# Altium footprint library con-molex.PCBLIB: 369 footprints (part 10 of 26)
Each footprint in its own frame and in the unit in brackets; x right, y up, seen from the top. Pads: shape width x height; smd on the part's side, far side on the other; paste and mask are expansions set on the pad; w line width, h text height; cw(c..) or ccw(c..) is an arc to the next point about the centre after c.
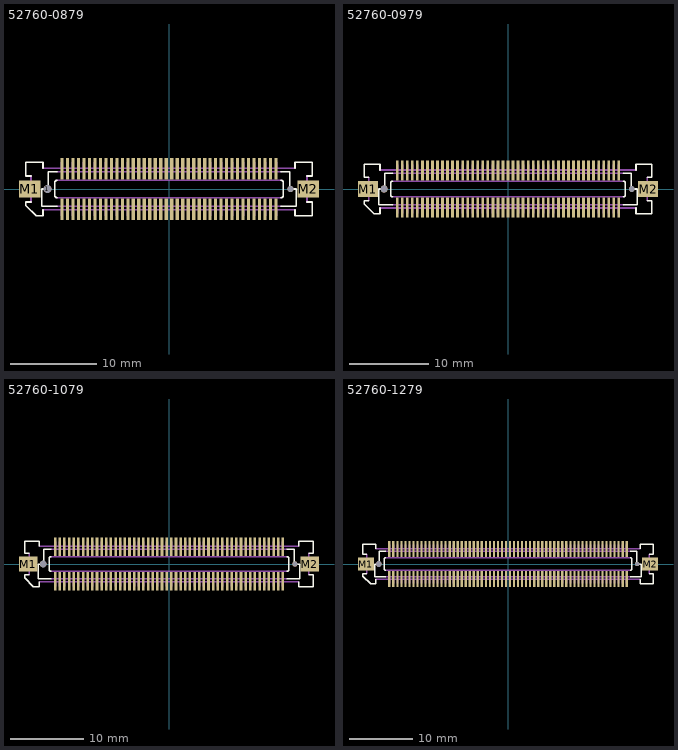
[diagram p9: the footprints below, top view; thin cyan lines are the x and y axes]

## 52760-0879 [mm]
pads (84):
  round 0.9 hole 0.9: 1(-14.035,0)
  rect 0.35x2.5 smd: 1(-12.383,-2.35) 2(-12.383,2.35) 3(-11.747,-2.35) 4(-11.747,2.35) 5(-11.112,-2.35) 6(-11.112,2.35) 7(-10.477,-2.35) 8(-10.477,2.35) 9(-9.842,-2.35) 10(-9.842,2.35) 11(-9.207,-2.35) 12(-9.207,2.35) 13(-8.572,-2.35) 14(-8.572,2.35) 15(-7.938,-2.35) 16(-7.938,2.35) 17(-7.302,-2.35) 18(-7.302,2.35) 19(-6.667,-2.35) 20(-6.667,2.35) 21(-6.032,-2.35) 22(-6.032,2.35) 23(-5.397,-2.35) 24(-5.397,2.35) 25(-4.763,-2.35) 26(-4.763,2.35) 27(-4.127,-2.35) 28(-4.127,2.35) 29(-3.492,-2.35) 30(-3.492,2.35) 31(-2.857,-2.35) 32(-2.857,2.35) 33(-2.222,-2.35) 34(-2.222,2.35) 35(-1.587,-2.35) 36(-1.587,2.35) 37(-0.953,-2.35) 38(-0.953,2.35) 39(-0.318,-2.35) 40(-0.318,2.35) 41(0.318,-2.35) 42(0.318,2.35) 43(0.953,-2.35) 44(0.953,2.35) 45(1.587,-2.35) 46(1.587,2.35) 47(2.222,-2.35) 48(2.222,2.35) 49(2.857,-2.35) 50(2.857,2.35) 51(3.492,-2.35) 52(3.492,2.35) 53(4.127,-2.35) 54(4.127,2.35) 55(4.763,-2.35) 56(4.763,2.35) 57(5.397,-2.35) 58(5.397,2.35) 59(6.032,-2.35) 60(6.032,2.35) 61(6.667,-2.35) 62(6.667,2.35) 63(7.302,-2.35) 64(7.302,2.35) 65(7.938,-2.35) 66(7.938,2.35) 67(8.572,-2.35) 68(8.572,2.35) 69(9.207,-2.35) 70(9.207,2.35) 71(9.842,-2.35) 72(9.842,2.35) 73(10.477,-2.35) 74(10.477,2.35) 75(11.112,-2.35) 76(11.112,2.35) 77(11.747,-2.35) 78(11.747,2.35) 79(12.383,-2.35) 80(12.383,2.35)
  round 0.7 hole 0.7: 1(14.035,0)
  rect 2.5x2 smd: M1(-16.075,0) M2(16.075,0)
Top Overlay:
  lines w0.203: -15.95,-1.5 -16.55,-1.5 -16.55,-1.9 -15.35,-3.1 -14.55,-3.1 -14.55,-2.4 ; -15.95,1.5 -16.55,1.5 -16.55,3.1 -14.55,3.1 -14.55,2.4 ; -12.95,-2 -14.7,-2 -14.7,0 -13.95,0 -13.95,2 -12.95,2 ; -12.95,-1 cw(c-12.95,-0.75) -13.2,-0.75 -13.2,0.75 cw(c-12.95,0.75) -12.95,1 ; 12.95,-2 14.7,-2 14.7,0 13.95,0 13.95,2 12.95,2 ; 12.95,-1 ccw(c12.95,-0.75) 13.2,-0.75 13.2,0.75 ccw(c12.95,0.75) 12.95,1 ; 14.55,-2.4 14.55,-3.1 16.55,-3.1 16.55,-1.5 15.95,-1.5 ; 14.55,2.4 14.55,3.1 16.55,3.1 16.55,1.5 15.95,1.5
Top Solder:
  rectangle: -12.582,-3.625 -12.183,-1.075
  region: -12.183,3.625 -12.582,3.625 -12.582,1.075 -12.183,1.075
  rectangle: -11.947,-3.625 -11.548,-1.075
  region: -11.548,3.625 -11.947,3.625 -11.947,1.075 -11.548,1.075
  rectangle: -11.312,-3.625 -10.913,-1.075
  region: -10.913,3.625 -11.312,3.625 -11.312,1.075 -10.913,1.075
  rectangle: -10.677,-3.625 -10.278,-1.075
  region: -10.278,3.625 -10.677,3.625 -10.677,1.075 -10.278,1.075
  rectangle: -10.042,-3.625 -9.643,-1.075
  region: -9.643,3.625 -10.042,3.625 -10.042,1.075 -9.643,1.075
  rectangle: -9.407,-3.625 -9.008,-1.075
  region: -9.008,3.625 -9.407,3.625 -9.407,1.075 -9.008,1.075
  rectangle: -8.772,-3.625 -8.373,-1.075
  region: -8.373,3.625 -8.772,3.625 -8.772,1.075 -8.373,1.075
  rectangle: -8.137,-3.625 -7.738,-1.075
  region: -7.738,3.625 -8.137,3.625 -8.137,1.075 -7.738,1.075
  rectangle: -7.502,-3.625 -7.103,-1.075
  region: -7.103,3.625 -7.502,3.625 -7.502,1.075 -7.103,1.075
  rectangle: -6.867,-3.625 -6.468,-1.075
  region: -6.468,3.625 -6.867,3.625 -6.867,1.075 -6.468,1.075
  rectangle: -6.232,-3.625 -5.833,-1.075
  region: -5.833,3.625 -6.232,3.625 -6.232,1.075 -5.833,1.075
  rectangle: -5.597,-3.625 -5.198,-1.075
  region: -5.198,3.625 -5.597,3.625 -5.597,1.075 -5.198,1.075
  rectangle: -4.962,-3.625 -4.563,-1.075
  region: -4.563,3.625 -4.962,3.625 -4.962,1.075 -4.563,1.075
  rectangle: -4.327,-3.625 -3.928,-1.075
  region: -3.928,3.625 -4.327,3.625 -4.327,1.075 -3.928,1.075
  rectangle: -3.692,-3.625 -3.293,-1.075
  region: -3.293,3.625 -3.692,3.625 -3.692,1.075 -3.293,1.075
  rectangle: -3.057,-3.625 -2.658,-1.075
  region: -2.658,3.625 -3.057,3.625 -3.057,1.075 -2.658,1.075
  rectangle: -2.422,-3.625 -2.023,-1.075
  region: -2.023,3.625 -2.422,3.625 -2.422,1.075 -2.023,1.075
  rectangle: -1.787,-3.625 -1.388,-1.075
  region: -1.388,3.625 -1.787,3.625 -1.787,1.075 -1.388,1.075
  rectangle: -1.152,-3.625 -0.753,-1.075
  region: -0.753,3.625 -1.152,3.625 -1.152,1.075 -0.753,1.075
  rectangle: -0.517,-3.625 -0.118,-1.075
  region: -0.118,3.625 -0.517,3.625 -0.517,1.075 -0.118,1.075
  rectangle: 0.118,-3.625 0.517,-1.075
  region: 0.517,3.625 0.118,3.625 0.118,1.075 0.517,1.075
  rectangle: 0.753,-3.625 1.152,-1.075
  region: 1.152,3.625 0.753,3.625 0.753,1.075 1.152,1.075
  rectangle: 1.388,-3.625 1.787,-1.075
  region: 1.787,3.625 1.388,3.625 1.388,1.075 1.787,1.075
  rectangle: 2.023,-3.625 2.422,-1.075
  region: 2.422,3.625 2.023,3.625 2.023,1.075 2.422,1.075
  rectangle: 2.658,-3.625 3.057,-1.075
  region: 3.057,3.625 2.658,3.625 2.658,1.075 3.057,1.075
  rectangle: 3.293,-3.625 3.692,-1.075
  region: 3.692,3.625 3.293,3.625 3.293,1.075 3.692,1.075
  rectangle: 3.928,-3.625 4.327,-1.075
  region: 4.327,3.625 3.928,3.625 3.928,1.075 4.327,1.075
  rectangle: 4.563,-3.625 4.962,-1.075
  region: 4.962,3.625 4.563,3.625 4.563,1.075 4.962,1.075
  rectangle: 5.198,-3.625 5.597,-1.075
  region: 5.597,3.625 5.198,3.625 5.198,1.075 5.597,1.075
  rectangle: 5.833,-3.625 6.232,-1.075
  region: 6.232,3.625 5.833,3.625 5.833,1.075 6.232,1.075
  rectangle: 6.468,-3.625 6.867,-1.075
  region: 6.867,3.625 6.468,3.625 6.468,1.075 6.867,1.075
  rectangle: 7.103,-3.625 7.502,-1.075
  region: 7.502,3.625 7.103,3.625 7.103,1.075 7.502,1.075
  rectangle: 7.738,-3.625 8.137,-1.075
  region: 8.137,3.625 7.738,3.625 7.738,1.075 8.137,1.075
  rectangle: 8.373,-3.625 8.772,-1.075
  region: 8.772,3.625 8.373,3.625 8.373,1.075 8.772,1.075
  rectangle: 9.008,-3.625 9.407,-1.075
  region: 9.407,3.625 9.008,3.625 9.008,1.075 9.407,1.075
  rectangle: 9.643,-3.625 10.042,-1.075
  region: 10.042,3.625 9.643,3.625 9.643,1.075 10.042,1.075
  rectangle: 10.278,-3.625 10.677,-1.075
  region: 10.677,3.625 10.278,3.625 10.278,1.075 10.677,1.075
  rectangle: 10.913,-3.625 11.312,-1.075
  region: 11.312,3.625 10.913,3.625 10.913,1.075 11.312,1.075
  rectangle: 11.548,-3.625 11.947,-1.075
  region: 11.947,3.625 11.548,3.625 11.548,1.075 11.947,1.075
  rectangle: 12.183,-3.625 12.582,-1.075
  region: 12.582,3.625 12.183,3.625 12.183,1.075 12.582,1.075
Mechanical 16:
  rectangle: -12.533,-3.1 -12.232,-2.375
  region: -12.232,3.1 -12.533,3.1 -12.533,2.375 -12.232,2.375
  rectangle: -11.898,-3.1 -11.597,-2.375
  region: -11.597,3.1 -11.898,3.1 -11.898,2.375 -11.597,2.375
  rectangle: -11.263,-3.1 -10.962,-2.375
  region: -10.962,3.1 -11.263,3.1 -11.263,2.375 -10.962,2.375
  rectangle: -10.628,-3.1 -10.327,-2.375
  region: -10.327,3.1 -10.628,3.1 -10.628,2.375 -10.327,2.375
  rectangle: -9.993,-3.1 -9.692,-2.375
  region: -9.692,3.1 -9.993,3.1 -9.993,2.375 -9.692,2.375
  rectangle: -9.358,-3.1 -9.057,-2.375
  region: -9.057,3.1 -9.358,3.1 -9.358,2.375 -9.057,2.375
  rectangle: -8.723,-3.1 -8.422,-2.375
  region: -8.422,3.1 -8.723,3.1 -8.723,2.375 -8.422,2.375
  rectangle: -8.088,-3.1 -7.787,-2.375
  region: -7.787,3.1 -8.088,3.1 -8.088,2.375 -7.787,2.375
  rectangle: -7.453,-3.1 -7.152,-2.375
  region: -7.152,3.1 -7.453,3.1 -7.453,2.375 -7.152,2.375
  rectangle: -6.818,-3.1 -6.517,-2.375
  region: -6.517,3.1 -6.818,3.1 -6.818,2.375 -6.517,2.375
  rectangle: -6.183,-3.1 -5.882,-2.375
  region: -5.882,3.1 -6.183,3.1 -6.183,2.375 -5.882,2.375
  rectangle: -5.548,-3.1 -5.247,-2.375
  region: -5.247,3.1 -5.548,3.1 -5.548,2.375 -5.247,2.375
  rectangle: -4.913,-3.1 -4.612,-2.375
  region: -4.612,3.1 -4.913,3.1 -4.913,2.375 -4.612,2.375
  rectangle: -4.278,-3.1 -3.977,-2.375
  region: -3.977,3.1 -4.278,3.1 -4.278,2.375 -3.977,2.375
  rectangle: -3.643,-3.1 -3.342,-2.375
  region: -3.342,3.1 -3.643,3.1 -3.643,2.375 -3.342,2.375
  rectangle: -3.008,-3.1 -2.707,-2.375
  region: -2.707,3.1 -3.008,3.1 -3.008,2.375 -2.707,2.375
  rectangle: -2.373,-3.1 -2.072,-2.375
  region: -2.072,3.1 -2.373,3.1 -2.373,2.375 -2.072,2.375
  rectangle: -1.738,-3.1 -1.437,-2.375
  region: -1.437,3.1 -1.738,3.1 -1.738,2.375 -1.437,2.375
  rectangle: -1.103,-3.1 -0.802,-2.375
  region: -0.802,3.1 -1.103,3.1 -1.103,2.375 -0.802,2.375
  rectangle: -0.468,-3.1 -0.167,-2.375
  region: -0.167,3.1 -0.468,3.1 -0.468,2.375 -0.167,2.375
  rectangle: 0.167,-3.1 0.468,-2.375
  region: 0.468,3.1 0.167,3.1 0.167,2.375 0.468,2.375
  rectangle: 0.802,-3.1 1.103,-2.375
  region: 1.103,3.1 0.802,3.1 0.802,2.375 1.103,2.375
  rectangle: 1.437,-3.1 1.738,-2.375
  region: 1.738,3.1 1.437,3.1 1.437,2.375 1.738,2.375
  rectangle: 2.072,-3.1 2.373,-2.375
  region: 2.373,3.1 2.072,3.1 2.072,2.375 2.373,2.375
  rectangle: 2.707,-3.1 3.008,-2.375
  region: 3.008,3.1 2.707,3.1 2.707,2.375 3.008,2.375
  rectangle: 3.342,-3.1 3.643,-2.375
  region: 3.643,3.1 3.342,3.1 3.342,2.375 3.643,2.375
  rectangle: 3.977,-3.1 4.278,-2.375
  region: 4.278,3.1 3.977,3.1 3.977,2.375 4.278,2.375
  rectangle: 4.612,-3.1 4.913,-2.375
  region: 4.913,3.1 4.612,3.1 4.612,2.375 4.913,2.375
  rectangle: 5.247,-3.1 5.548,-2.375
  region: 5.548,3.1 5.247,3.1 5.247,2.375 5.548,2.375
  rectangle: 5.882,-3.1 6.183,-2.375
  region: 6.183,3.1 5.882,3.1 5.882,2.375 6.183,2.375
  rectangle: 6.517,-3.1 6.818,-2.375
  region: 6.818,3.1 6.517,3.1 6.517,2.375 6.818,2.375
  rectangle: 7.152,-3.1 7.453,-2.375
  region: 7.453,3.1 7.152,3.1 7.152,2.375 7.453,2.375
  rectangle: 7.787,-3.1 8.088,-2.375
  region: 8.088,3.1 7.787,3.1 7.787,2.375 8.088,2.375
  rectangle: 8.422,-3.1 8.723,-2.375
  region: 8.723,3.1 8.422,3.1 8.422,2.375 8.723,2.375
  rectangle: 9.057,-3.1 9.358,-2.375
  region: 9.358,3.1 9.057,3.1 9.057,2.375 9.358,2.375
  rectangle: 9.692,-3.1 9.993,-2.375
  region: 9.993,3.1 9.692,3.1 9.692,2.375 9.993,2.375
  rectangle: 10.327,-3.1 10.628,-2.375
  region: 10.628,3.1 10.327,3.1 10.327,2.375 10.628,2.375
  rectangle: 10.962,-3.1 11.263,-2.375
  region: 11.263,3.1 10.962,3.1 10.962,2.375 11.263,2.375
  rectangle: 11.597,-3.1 11.898,-2.375
  region: 11.898,3.1 11.597,3.1 11.597,2.375 11.898,2.375
  rectangle: 12.232,-3.1 12.533,-2.375
  region: 12.533,3.1 12.232,3.1 12.232,2.375 12.533,2.375
  lines w0.203: -15.95,-1.5 -15.95,1.5 ; -14.55,-2.4 14.55,-2.4 ; -14.55,2.4 14.55,2.4 ; -12.95,-2 12.95,-2 ; -12.95,-1 12.95,-1 ; -12.95,1 12.95,1 ; -12.95,2 12.95,2 ; 15.95,-1.5 15.95,1.5

## 52760-0979 [mm]
pads (94):
  round 0.9 hole 0.9: 1(-15.623,0)
  rect 0.35x2.5 smd: 1(-13.97,-2.35) 2(-13.97,2.35) 3(-13.335,-2.35) 4(-13.335,2.35) 5(-12.7,-2.35) 6(-12.7,2.35) 7(-12.065,-2.35) 8(-12.065,2.35) 9(-11.43,-2.35) 10(-11.43,2.35) 11(-10.795,-2.35) 12(-10.795,2.35) 13(-10.16,-2.35) 14(-10.16,2.35) 15(-9.525,-2.35) 16(-9.525,2.35) 17(-8.89,-2.35) 18(-8.89,2.35) 19(-8.255,-2.35) 20(-8.255,2.35) 21(-7.62,-2.35) 22(-7.62,2.35) 23(-6.985,-2.35) 24(-6.985,2.35) 25(-6.35,-2.35) 26(-6.35,2.35) 27(-5.715,-2.35) 28(-5.715,2.35) 29(-5.08,-2.35) 30(-5.08,2.35) 31(-4.445,-2.35) 32(-4.445,2.35) 33(-3.81,-2.35) 34(-3.81,2.35) 35(-3.175,-2.35) 36(-3.175,2.35) 37(-2.54,-2.35) 38(-2.54,2.35) 39(-1.905,-2.35) 40(-1.905,2.35) 41(-1.27,-2.35) 42(-1.27,2.35) 43(-0.635,-2.35) 44(-0.635,2.35) 45(0,-2.35) 46(0,2.35) 47(0.635,-2.35) 48(0.635,2.35) 49(1.27,-2.35) 50(1.27,2.35) 51(1.905,-2.35) 52(1.905,2.35) 53(2.54,-2.35) 54(2.54,2.35) 55(3.175,-2.35) 56(3.175,2.35) 57(3.81,-2.35) 58(3.81,2.35) 59(4.445,-2.35) 60(4.445,2.35) 61(5.08,-2.35) 62(5.08,2.35) 63(5.715,-2.35) 64(5.715,2.35) 65(6.35,-2.35) 66(6.35,2.35) 67(6.985,-2.35) 68(6.985,2.35) 69(7.62,-2.35) 70(7.62,2.35) 71(8.255,-2.35) 72(8.255,2.35) 73(8.89,-2.35) 74(8.89,2.35) 75(9.525,-2.35) 76(9.525,2.35) 77(10.16,-2.35) 78(10.16,2.35) 79(10.795,-2.35) 80(10.795,2.35) 81(11.43,-2.35) 82(11.43,2.35) 83(12.065,-2.35) 84(12.065,2.35) 85(12.7,-2.35) 86(12.7,2.35) 87(13.335,-2.35) 88(13.335,2.35) 89(13.97,-2.35) 90(13.97,2.35)
  round 0.7 hole 0.7: 1(15.623,0)
  rect 2.5x2 smd: M1(-17.662,0) M2(17.662,0)
Top Overlay:
  lines w0.203: -17.537,-1.5 -18.137,-1.5 -18.137,-1.9 -16.937,-3.1 -16.137,-3.1 -16.137,-2.4 ; -17.537,1.5 -18.137,1.5 -18.137,3.1 -16.137,3.1 -16.137,2.4 ; -14.537,-2 -16.287,-2 -16.287,0 -15.537,0 -15.537,2 -14.537,2 ; -14.537,-1 cw(c-14.538,-0.75) -14.788,-0.75 -14.788,0.75 cw(c-14.538,0.75) -14.537,1 ; 14.537,-2 16.287,-2 16.287,0 15.537,0 15.537,2 14.537,2 ; 14.537,-1 ccw(c14.538,-0.75) 14.788,-0.75 14.788,0.75 ccw(c14.538,0.75) 14.537,1 ; 16.137,-2.4 16.137,-3.1 18.137,-3.1 18.137,-1.5 17.537,-1.5 ; 16.137,2.4 16.137,3.1 18.137,3.1 18.137,1.5 17.537,1.5
Top Solder:
  rectangle: -14.17,-3.625 -13.77,-1.075
  region: -13.77,3.625 -14.17,3.625 -14.17,1.075 -13.77,1.075
  rectangle: -13.535,-3.625 -13.135,-1.075
  region: -13.135,3.625 -13.535,3.625 -13.535,1.075 -13.135,1.075
  rectangle: -12.9,-3.625 -12.5,-1.075
  region: -12.5,3.625 -12.9,3.625 -12.9,1.075 -12.5,1.075
  rectangle: -12.265,-3.625 -11.865,-1.075
  region: -11.865,3.625 -12.265,3.625 -12.265,1.075 -11.865,1.075
  rectangle: -11.63,-3.625 -11.23,-1.075
  region: -11.23,3.625 -11.63,3.625 -11.63,1.075 -11.23,1.075
  rectangle: -10.995,-3.625 -10.595,-1.075
  region: -10.595,3.625 -10.995,3.625 -10.995,1.075 -10.595,1.075
  rectangle: -10.36,-3.625 -9.96,-1.075
  region: -9.96,3.625 -10.36,3.625 -10.36,1.075 -9.96,1.075
  rectangle: -9.725,-3.625 -9.325,-1.075
  region: -9.325,3.625 -9.725,3.625 -9.725,1.075 -9.325,1.075
  rectangle: -9.09,-3.625 -8.69,-1.075
  region: -8.69,3.625 -9.09,3.625 -9.09,1.075 -8.69,1.075
  rectangle: -8.455,-3.625 -8.055,-1.075
  region: -8.055,3.625 -8.455,3.625 -8.455,1.075 -8.055,1.075
  rectangle: -7.82,-3.625 -7.42,-1.075
  region: -7.42,3.625 -7.82,3.625 -7.82,1.075 -7.42,1.075
  rectangle: -7.185,-3.625 -6.785,-1.075
  region: -6.785,3.625 -7.185,3.625 -7.185,1.075 -6.785,1.075
  rectangle: -6.55,-3.625 -6.15,-1.075
  region: -6.15,3.625 -6.55,3.625 -6.55,1.075 -6.15,1.075
  rectangle: -5.915,-3.625 -5.515,-1.075
  region: -5.515,3.625 -5.915,3.625 -5.915,1.075 -5.515,1.075
  rectangle: -5.28,-3.625 -4.88,-1.075
  region: -4.88,3.625 -5.28,3.625 -5.28,1.075 -4.88,1.075
  rectangle: -4.645,-3.625 -4.245,-1.075
  region: -4.245,3.625 -4.645,3.625 -4.645,1.075 -4.245,1.075
  rectangle: -4.01,-3.625 -3.61,-1.075
  region: -3.61,3.625 -4.01,3.625 -4.01,1.075 -3.61,1.075
  rectangle: -3.375,-3.625 -2.975,-1.075
  region: -2.975,3.625 -3.375,3.625 -3.375,1.075 -2.975,1.075
  rectangle: -2.74,-3.625 -2.34,-1.075
  region: -2.34,3.625 -2.74,3.625 -2.74,1.075 -2.34,1.075
  rectangle: -2.105,-3.625 -1.705,-1.075
  region: -1.705,3.625 -2.105,3.625 -2.105,1.075 -1.705,1.075
  rectangle: -1.47,-3.625 -1.07,-1.075
  region: -1.07,3.625 -1.47,3.625 -1.47,1.075 -1.07,1.075
  rectangle: -0.835,-3.625 -0.435,-1.075
  region: -0.435,3.625 -0.835,3.625 -0.835,1.075 -0.435,1.075
  rectangle: -0.2,-3.625 0.2,-1.075
  region: 0.2,3.625 -0.2,3.625 -0.2,1.075 0.2,1.075
  rectangle: 0.435,-3.625 0.835,-1.075
  region: 0.835,3.625 0.435,3.625 0.435,1.075 0.835,1.075
  rectangle: 1.07,-3.625 1.47,-1.075
  region: 1.47,3.625 1.07,3.625 1.07,1.075 1.47,1.075
  rectangle: 1.705,-3.625 2.105,-1.075
  region: 2.105,3.625 1.705,3.625 1.705,1.075 2.105,1.075
  rectangle: 2.34,-3.625 2.74,-1.075
  region: 2.74,3.625 2.34,3.625 2.34,1.075 2.74,1.075
  rectangle: 2.975,-3.625 3.375,-1.075
  region: 3.375,3.625 2.975,3.625 2.975,1.075 3.375,1.075
  rectangle: 3.61,-3.625 4.01,-1.075
  region: 4.01,3.625 3.61,3.625 3.61,1.075 4.01,1.075
  rectangle: 4.245,-3.625 4.645,-1.075
  region: 4.645,3.625 4.245,3.625 4.245,1.075 4.645,1.075
  rectangle: 4.88,-3.625 5.28,-1.075
  region: 5.28,3.625 4.88,3.625 4.88,1.075 5.28,1.075
  rectangle: 5.515,-3.625 5.915,-1.075
  region: 5.915,3.625 5.515,3.625 5.515,1.075 5.915,1.075
  rectangle: 6.15,-3.625 6.55,-1.075
  region: 6.55,3.625 6.15,3.625 6.15,1.075 6.55,1.075
  rectangle: 6.785,-3.625 7.185,-1.075
  region: 7.185,3.625 6.785,3.625 6.785,1.075 7.185,1.075
  rectangle: 7.42,-3.625 7.82,-1.075
  region: 7.82,3.625 7.42,3.625 7.42,1.075 7.82,1.075
  rectangle: 8.055,-3.625 8.455,-1.075
  region: 8.455,3.625 8.055,3.625 8.055,1.075 8.455,1.075
  rectangle: 8.69,-3.625 9.09,-1.075
  region: 9.09,3.625 8.69,3.625 8.69,1.075 9.09,1.075
  rectangle: 9.325,-3.625 9.725,-1.075
  region: 9.725,3.625 9.325,3.625 9.325,1.075 9.725,1.075
  rectangle: 9.96,-3.625 10.36,-1.075
  region: 10.36,3.625 9.96,3.625 9.96,1.075 10.36,1.075
  rectangle: 10.595,-3.625 10.995,-1.075
  region: 10.995,3.625 10.595,3.625 10.595,1.075 10.995,1.075
  rectangle: 11.23,-3.625 11.63,-1.075
  region: 11.63,3.625 11.23,3.625 11.23,1.075 11.63,1.075
  rectangle: 11.865,-3.625 12.265,-1.075
  region: 12.265,3.625 11.865,3.625 11.865,1.075 12.265,1.075
  rectangle: 12.5,-3.625 12.9,-1.075
  region: 12.9,3.625 12.5,3.625 12.5,1.075 12.9,1.075
  rectangle: 13.135,-3.625 13.535,-1.075
  region: 13.535,3.625 13.135,3.625 13.135,1.075 13.535,1.075
  rectangle: 13.77,-3.625 14.17,-1.075
  region: 14.17,3.625 13.77,3.625 13.77,1.075 14.17,1.075
Mechanical 16:
  rectangle: -14.12,-3.1 -13.82,-2.375
  region: -13.82,3.1 -14.12,3.1 -14.12,2.375 -13.82,2.375
  rectangle: -13.485,-3.1 -13.185,-2.375
  region: -13.185,3.1 -13.485,3.1 -13.485,2.375 -13.185,2.375
  rectangle: -12.85,-3.1 -12.55,-2.375
  region: -12.55,3.1 -12.85,3.1 -12.85,2.375 -12.55,2.375
  rectangle: -12.215,-3.1 -11.915,-2.375
  region: -11.915,3.1 -12.215,3.1 -12.215,2.375 -11.915,2.375
  rectangle: -11.58,-3.1 -11.28,-2.375
  region: -11.28,3.1 -11.58,3.1 -11.58,2.375 -11.28,2.375
  rectangle: -10.945,-3.1 -10.645,-2.375
  region: -10.645,3.1 -10.945,3.1 -10.945,2.375 -10.645,2.375
  rectangle: -10.31,-3.1 -10.01,-2.375
  region: -10.01,3.1 -10.31,3.1 -10.31,2.375 -10.01,2.375
  rectangle: -9.675,-3.1 -9.375,-2.375
  region: -9.375,3.1 -9.675,3.1 -9.675,2.375 -9.375,2.375
  rectangle: -9.04,-3.1 -8.74,-2.375
  region: -8.74,3.1 -9.04,3.1 -9.04,2.375 -8.74,2.375
  rectangle: -8.405,-3.1 -8.105,-2.375
  region: -8.105,3.1 -8.405,3.1 -8.405,2.375 -8.105,2.375
  rectangle: -7.77,-3.1 -7.47,-2.375
  region: -7.47,3.1 -7.77,3.1 -7.77,2.375 -7.47,2.375
  rectangle: -7.135,-3.1 -6.835,-2.375
  region: -6.835,3.1 -7.135,3.1 -7.135,2.375 -6.835,2.375
  rectangle: -6.5,-3.1 -6.2,-2.375
  region: -6.2,3.1 -6.5,3.1 -6.5,2.375 -6.2,2.375
  rectangle: -5.865,-3.1 -5.565,-2.375
  region: -5.565,3.1 -5.865,3.1 -5.865,2.375 -5.565,2.375
  rectangle: -5.23,-3.1 -4.93,-2.375
  region: -4.93,3.1 -5.23,3.1 -5.23,2.375 -4.93,2.375
  rectangle: -4.595,-3.1 -4.295,-2.375
  region: -4.295,3.1 -4.595,3.1 -4.595,2.375 -4.295,2.375
  rectangle: -3.96,-3.1 -3.66,-2.375
  region: -3.66,3.1 -3.96,3.1 -3.96,2.375 -3.66,2.375
  rectangle: -3.325,-3.1 -3.025,-2.375
  region: -3.025,3.1 -3.325,3.1 -3.325,2.375 -3.025,2.375
  rectangle: -2.69,-3.1 -2.39,-2.375
  region: -2.39,3.1 -2.69,3.1 -2.69,2.375 -2.39,2.375
  rectangle: -2.055,-3.1 -1.755,-2.375
  region: -1.755,3.1 -2.055,3.1 -2.055,2.375 -1.755,2.375
  rectangle: -1.42,-3.1 -1.12,-2.375
  region: -1.12,3.1 -1.42,3.1 -1.42,2.375 -1.12,2.375
  rectangle: -0.785,-3.1 -0.485,-2.375
  region: -0.485,3.1 -0.785,3.1 -0.785,2.375 -0.485,2.375
  rectangle: -0.15,-3.1 0.15,-2.375
  region: 0.15,3.1 -0.15,3.1 -0.15,2.375 0.15,2.375
  rectangle: 0.485,-3.1 0.785,-2.375
  region: 0.785,3.1 0.485,3.1 0.485,2.375 0.785,2.375
  rectangle: 1.12,-3.1 1.42,-2.375
  region: 1.42,3.1 1.12,3.1 1.12,2.375 1.42,2.375
  rectangle: 1.755,-3.1 2.055,-2.375
  region: 2.055,3.1 1.755,3.1 1.755,2.375 2.055,2.375
  rectangle: 2.39,-3.1 2.69,-2.375
  region: 2.69,3.1 2.39,3.1 2.39,2.375 2.69,2.375
  rectangle: 3.025,-3.1 3.325,-2.375
  region: 3.325,3.1 3.025,3.1 3.025,2.375 3.325,2.375
  rectangle: 3.66,-3.1 3.96,-2.375
  region: 3.96,3.1 3.66,3.1 3.66,2.375 3.96,2.375
  rectangle: 4.295,-3.1 4.595,-2.375
  region: 4.595,3.1 4.295,3.1 4.295,2.375 4.595,2.375
  rectangle: 4.93,-3.1 5.23,-2.375
  region: 5.23,3.1 4.93,3.1 4.93,2.375 5.23,2.375
  rectangle: 5.565,-3.1 5.865,-2.375
  region: 5.865,3.1 5.565,3.1 5.565,2.375 5.865,2.375
  rectangle: 6.2,-3.1 6.5,-2.375
  region: 6.5,3.1 6.2,3.1 6.2,2.375 6.5,2.375
  rectangle: 6.835,-3.1 7.135,-2.375
  region: 7.135,3.1 6.835,3.1 6.835,2.375 7.135,2.375
  rectangle: 7.47,-3.1 7.77,-2.375
  region: 7.77,3.1 7.47,3.1 7.47,2.375 7.77,2.375
  rectangle: 8.105,-3.1 8.405,-2.375
  region: 8.405,3.1 8.105,3.1 8.105,2.375 8.405,2.375
  rectangle: 8.74,-3.1 9.04,-2.375
  region: 9.04,3.1 8.74,3.1 8.74,2.375 9.04,2.375
  rectangle: 9.375,-3.1 9.675,-2.375
  region: 9.675,3.1 9.375,3.1 9.375,2.375 9.675,2.375
  rectangle: 10.01,-3.1 10.31,-2.375
  region: 10.31,3.1 10.01,3.1 10.01,2.375 10.31,2.375
  rectangle: 10.645,-3.1 10.945,-2.375
  region: 10.945,3.1 10.645,3.1 10.645,2.375 10.945,2.375
  rectangle: 11.28,-3.1 11.58,-2.375
  region: 11.58,3.1 11.28,3.1 11.28,2.375 11.58,2.375
  rectangle: 11.915,-3.1 12.215,-2.375
  region: 12.215,3.1 11.915,3.1 11.915,2.375 12.215,2.375
  rectangle: 12.55,-3.1 12.85,-2.375
  region: 12.85,3.1 12.55,3.1 12.55,2.375 12.85,2.375
  rectangle: 13.185,-3.1 13.485,-2.375
  region: 13.485,3.1 13.185,3.1 13.185,2.375 13.485,2.375
  rectangle: 13.82,-3.1 14.12,-2.375
  region: 14.12,3.1 13.82,3.1 13.82,2.375 14.12,2.375
  lines w0.203: -17.537,-1.5 -17.537,1.5 ; -16.137,-2.4 16.137,-2.4 ; -16.137,2.4 16.137,2.4 ; -14.537,-2 14.537,-2 ; -14.537,-1 14.537,-1 ; -14.537,1 14.537,1 ; -14.537,2 14.537,2 ; 17.537,-1.5 17.537,1.5

## 52760-1079 [mm]
pads (104):
  round 0.9 hole 0.9: 1(-17.21,0)
  rect 0.35x2.5 smd: 1(-15.557,-2.35) 2(-15.557,2.35) 3(-14.922,-2.35) 4(-14.922,2.35) 5(-14.287,-2.35) 6(-14.287,2.35) 7(-13.652,-2.35) 8(-13.652,2.35) 9(-13.018,-2.35) 10(-13.018,2.35) 11(-12.383,-2.35) 12(-12.383,2.35) 13(-11.747,-2.35) 14(-11.747,2.35) 15(-11.112,-2.35) 16(-11.112,2.35) 17(-10.477,-2.35) 18(-10.477,2.35) 19(-9.842,-2.35) 20(-9.842,2.35) 21(-9.207,-2.35) 22(-9.207,2.35) 23(-8.572,-2.35) 24(-8.572,2.35) 25(-7.938,-2.35) 26(-7.938,2.35) 27(-7.302,-2.35) 28(-7.302,2.35) 29(-6.667,-2.35) 30(-6.667,2.35) 31(-6.032,-2.35) 32(-6.032,2.35) 33(-5.397,-2.35) 34(-5.397,2.35) 35(-4.763,-2.35) 36(-4.763,2.35) 37(-4.127,-2.35) 38(-4.127,2.35) 39(-3.492,-2.35) 40(-3.492,2.35) 41(-2.857,-2.35) 42(-2.857,2.35) 43(-2.222,-2.35) 44(-2.222,2.35) 45(-1.587,-2.35) 46(-1.587,2.35) 47(-0.953,-2.35) 48(-0.953,2.35) 49(-0.318,-2.35) 50(-0.318,2.35) 51(0.318,-2.35) 52(0.318,2.35) 53(0.953,-2.35) 54(0.953,2.35) 55(1.587,-2.35) 56(1.587,2.35) 57(2.222,-2.35) 58(2.222,2.35) 59(2.857,-2.35) 60(2.857,2.35) 61(3.492,-2.35) 62(3.492,2.35) 63(4.127,-2.35) 64(4.127,2.35) 65(4.763,-2.35) 66(4.763,2.35) 67(5.397,-2.35) 68(5.397,2.35) 69(6.032,-2.35) 70(6.032,2.35) 71(6.667,-2.35) 72(6.667,2.35) 73(7.302,-2.35) 74(7.302,2.35) 75(7.938,-2.35) 76(7.938,2.35) 77(8.572,-2.35) 78(8.572,2.35) 79(9.207,-2.35) 80(9.207,2.35) 81(9.842,-2.35) 82(9.842,2.35) 83(10.477,-2.35) 84(10.477,2.35) 85(11.112,-2.35) 86(11.112,2.35) 87(11.747,-2.35) 88(11.747,2.35) 89(12.383,-2.35) 90(12.383,2.35) 91(13.018,-2.35) 92(13.018,2.35) 93(13.652,-2.35) 94(13.652,2.35) 95(14.287,-2.35) 96(14.287,2.35) 97(14.922,-2.35) 98(14.922,2.35) 99(15.557,-2.35) 100(15.557,2.35)
  round 0.7 hole 0.7: 1(17.21,0)
  rect 2.5x2 smd: M1(-19.25,0) M2(19.25,0)
Top Overlay:
  lines w0.203: -19.125,-1.5 -19.725,-1.5 -19.725,-1.9 -18.525,-3.1 -17.725,-3.1 -17.725,-2.4 ; -19.125,1.5 -19.725,1.5 -19.725,3.1 -17.725,3.1 -17.725,2.4 ; -16.125,-2 -17.875,-2 -17.875,0 -17.125,0 -17.125,2 -16.125,2 ; -16.125,-1 cw(c-16.125,-0.75) -16.375,-0.75 -16.375,0.75 cw(c-16.125,0.75) -16.125,1 ; 16.125,-2 17.875,-2 17.875,0 17.125,0 17.125,2 16.125,2 ; 16.125,-1 ccw(c16.125,-0.75) 16.375,-0.75 16.375,0.75 ccw(c16.125,0.75) 16.125,1 ; 17.725,-2.4 17.725,-3.1 19.725,-3.1 19.725,-1.5 19.125,-1.5 ; 17.725,2.4 17.725,3.1 19.725,3.1 19.725,1.5 19.125,1.5
Top Solder:
  rectangle: -15.757,-3.625 -15.358,-1.075
  region: -15.358,3.625 -15.757,3.625 -15.757,1.075 -15.358,1.075
  rectangle: -15.122,-3.625 -14.723,-1.075
  region: -14.723,3.625 -15.122,3.625 -15.122,1.075 -14.723,1.075
  rectangle: -14.487,-3.625 -14.088,-1.075
  region: -14.088,3.625 -14.487,3.625 -14.487,1.075 -14.088,1.075
  rectangle: -13.852,-3.625 -13.453,-1.075
  region: -13.453,3.625 -13.852,3.625 -13.852,1.075 -13.453,1.075
  rectangle: -13.217,-3.625 -12.818,-1.075
  region: -12.818,3.625 -13.217,3.625 -13.217,1.075 -12.818,1.075
  rectangle: -12.582,-3.625 -12.183,-1.075
  region: -12.183,3.625 -12.582,3.625 -12.582,1.075 -12.183,1.075
  rectangle: -11.947,-3.625 -11.548,-1.075
  region: -11.548,3.625 -11.947,3.625 -11.947,1.075 -11.548,1.075
  rectangle: -11.312,-3.625 -10.913,-1.075
  region: -10.913,3.625 -11.312,3.625 -11.312,1.075 -10.913,1.075
  rectangle: -10.677,-3.625 -10.278,-1.075
  region: -10.278,3.625 -10.677,3.625 -10.677,1.075 -10.278,1.075
  rectangle: -10.042,-3.625 -9.643,-1.075
  region: -9.643,3.625 -10.042,3.625 -10.042,1.075 -9.643,1.075
  rectangle: -9.407,-3.625 -9.008,-1.075
  region: -9.008,3.625 -9.407,3.625 -9.407,1.075 -9.008,1.075
  rectangle: -8.772,-3.625 -8.373,-1.075
  region: -8.373,3.625 -8.772,3.625 -8.772,1.075 -8.373,1.075
  rectangle: -8.137,-3.625 -7.738,-1.075
  region: -7.738,3.625 -8.137,3.625 -8.137,1.075 -7.738,1.075
  rectangle: -7.502,-3.625 -7.103,-1.075
  region: -7.103,3.625 -7.502,3.625 -7.502,1.075 -7.103,1.075
  rectangle: -6.867,-3.625 -6.468,-1.075
  region: -6.468,3.625 -6.867,3.625 -6.867,1.075 -6.468,1.075
  rectangle: -6.232,-3.625 -5.833,-1.075
  region: -5.833,3.625 -6.232,3.625 -6.232,1.075 -5.833,1.075
  rectangle: -5.597,-3.625 -5.198,-1.075
  region: -5.198,3.625 -5.597,3.625 -5.597,1.075 -5.198,1.075
  rectangle: -4.962,-3.625 -4.563,-1.075
  region: -4.563,3.625 -4.962,3.625 -4.962,1.075 -4.563,1.075
  rectangle: -4.327,-3.625 -3.928,-1.075
  region: -3.928,3.625 -4.327,3.625 -4.327,1.075 -3.928,1.075
  rectangle: -3.692,-3.625 -3.293,-1.075
  region: -3.293,3.625 -3.692,3.625 -3.692,1.075 -3.293,1.075
  rectangle: -3.057,-3.625 -2.658,-1.075
  region: -2.658,3.625 -3.057,3.625 -3.057,1.075 -2.658,1.075
  rectangle: -2.422,-3.625 -2.023,-1.075
  region: -2.023,3.625 -2.422,3.625 -2.422,1.075 -2.023,1.075
  rectangle: -1.787,-3.625 -1.388,-1.075
  region: -1.388,3.625 -1.787,3.625 -1.787,1.075 -1.388,1.075
  rectangle: -1.152,-3.625 -0.753,-1.075
  region: -0.753,3.625 -1.152,3.625 -1.152,1.075 -0.753,1.075
  rectangle: -0.517,-3.625 -0.118,-1.075
  region: -0.118,3.625 -0.517,3.625 -0.517,1.075 -0.118,1.075
  rectangle: 0.118,-3.625 0.517,-1.075
  region: 0.517,3.625 0.118,3.625 0.118,1.075 0.517,1.075
  rectangle: 0.753,-3.625 1.152,-1.075
  region: 1.152,3.625 0.753,3.625 0.753,1.075 1.152,1.075
  rectangle: 1.388,-3.625 1.787,-1.075
  region: 1.787,3.625 1.388,3.625 1.388,1.075 1.787,1.075
  rectangle: 2.023,-3.625 2.422,-1.075
  region: 2.422,3.625 2.023,3.625 2.023,1.075 2.422,1.075
  rectangle: 2.658,-3.625 3.057,-1.075
  region: 3.057,3.625 2.658,3.625 2.658,1.075 3.057,1.075
  rectangle: 3.293,-3.625 3.692,-1.075
  region: 3.692,3.625 3.293,3.625 3.293,1.075 3.692,1.075
  rectangle: 3.928,-3.625 4.327,-1.075
  region: 4.327,3.625 3.928,3.625 3.928,1.075 4.327,1.075
  rectangle: 4.563,-3.625 4.962,-1.075
  region: 4.962,3.625 4.563,3.625 4.563,1.075 4.962,1.075
  rectangle: 5.198,-3.625 5.597,-1.075
  region: 5.597,3.625 5.198,3.625 5.198,1.075 5.597,1.075
  rectangle: 5.833,-3.625 6.232,-1.075
  region: 6.232,3.625 5.833,3.625 5.833,1.075 6.232,1.075
  rectangle: 6.468,-3.625 6.867,-1.075
  region: 6.867,3.625 6.468,3.625 6.468,1.075 6.867,1.075
  rectangle: 7.103,-3.625 7.502,-1.075
  region: 7.502,3.625 7.103,3.625 7.103,1.075 7.502,1.075
  rectangle: 7.738,-3.625 8.137,-1.075
  region: 8.137,3.625 7.738,3.625 7.738,1.075 8.137,1.075
  rectangle: 8.373,-3.625 8.772,-1.075
  region: 8.772,3.625 8.373,3.625 8.373,1.075 8.772,1.075
  rectangle: 9.008,-3.625 9.407,-1.075
  region: 9.407,3.625 9.008,3.625 9.008,1.075 9.407,1.075
  rectangle: 9.643,-3.625 10.042,-1.075
  region: 10.042,3.625 9.643,3.625 9.643,1.075 10.042,1.075
  rectangle: 10.278,-3.625 10.677,-1.075
  region: 10.677,3.625 10.278,3.625 10.278,1.075 10.677,1.075
  rectangle: 10.913,-3.625 11.312,-1.075
  region: 11.312,3.625 10.913,3.625 10.913,1.075 11.312,1.075
  rectangle: 11.548,-3.625 11.947,-1.075
  region: 11.947,3.625 11.548,3.625 11.548,1.075 11.947,1.075
  rectangle: 12.183,-3.625 12.582,-1.075
  region: 12.582,3.625 12.183,3.625 12.183,1.075 12.582,1.075
  rectangle: 12.818,-3.625 13.217,-1.075
  region: 13.217,3.625 12.818,3.625 12.818,1.075 13.217,1.075
  rectangle: 13.453,-3.625 13.852,-1.075
  region: 13.852,3.625 13.453,3.625 13.453,1.075 13.852,1.075
  rectangle: 14.088,-3.625 14.487,-1.075
  region: 14.487,3.625 14.088,3.625 14.088,1.075 14.487,1.075
  rectangle: 14.723,-3.625 15.122,-1.075
  region: 15.122,3.625 14.723,3.625 14.723,1.075 15.122,1.075
  rectangle: 15.358,-3.625 15.757,-1.075
  region: 15.757,3.625 15.358,3.625 15.358,1.075 15.757,1.075
Mechanical 16:
  rectangle: -15.708,-3.1 -15.407,-2.375
  region: -15.407,3.1 -15.708,3.1 -15.708,2.375 -15.407,2.375
  rectangle: -15.073,-3.1 -14.772,-2.375
  region: -14.772,3.1 -15.073,3.1 -15.073,2.375 -14.772,2.375
  rectangle: -14.438,-3.1 -14.137,-2.375
  region: -14.137,3.1 -14.438,3.1 -14.438,2.375 -14.137,2.375
  rectangle: -13.803,-3.1 -13.502,-2.375
  region: -13.502,3.1 -13.803,3.1 -13.803,2.375 -13.502,2.375
  rectangle: -13.168,-3.1 -12.867,-2.375
  region: -12.867,3.1 -13.168,3.1 -13.168,2.375 -12.867,2.375
  rectangle: -12.533,-3.1 -12.232,-2.375
  region: -12.232,3.1 -12.533,3.1 -12.533,2.375 -12.232,2.375
  rectangle: -11.898,-3.1 -11.597,-2.375
  region: -11.597,3.1 -11.898,3.1 -11.898,2.375 -11.597,2.375
  rectangle: -11.263,-3.1 -10.962,-2.375
  region: -10.962,3.1 -11.263,3.1 -11.263,2.375 -10.962,2.375
  rectangle: -10.628,-3.1 -10.327,-2.375
  region: -10.327,3.1 -10.628,3.1 -10.628,2.375 -10.327,2.375
  rectangle: -9.993,-3.1 -9.692,-2.375
  region: -9.692,3.1 -9.993,3.1 -9.993,2.375 -9.692,2.375
  rectangle: -9.358,-3.1 -9.057,-2.375
  region: -9.057,3.1 -9.358,3.1 -9.358,2.375 -9.057,2.375
  rectangle: -8.723,-3.1 -8.422,-2.375
  region: -8.422,3.1 -8.723,3.1 -8.723,2.375 -8.422,2.375
  rectangle: -8.088,-3.1 -7.787,-2.375
  region: -7.787,3.1 -8.088,3.1 -8.088,2.375 -7.787,2.375
  rectangle: -7.453,-3.1 -7.152,-2.375
  region: -7.152,3.1 -7.453,3.1 -7.453,2.375 -7.152,2.375
  rectangle: -6.818,-3.1 -6.517,-2.375
  region: -6.517,3.1 -6.818,3.1 -6.818,2.375 -6.517,2.375
  rectangle: -6.183,-3.1 -5.882,-2.375
  region: -5.882,3.1 -6.183,3.1 -6.183,2.375 -5.882,2.375
  rectangle: -5.548,-3.1 -5.247,-2.375
  region: -5.247,3.1 -5.548,3.1 -5.548,2.375 -5.247,2.375
  rectangle: -4.913,-3.1 -4.612,-2.375
  region: -4.612,3.1 -4.913,3.1 -4.913,2.375 -4.612,2.375
  rectangle: -4.278,-3.1 -3.977,-2.375
  region: -3.977,3.1 -4.278,3.1 -4.278,2.375 -3.977,2.375
  rectangle: -3.643,-3.1 -3.342,-2.375
  region: -3.342,3.1 -3.643,3.1 -3.643,2.375 -3.342,2.375
  rectangle: -3.008,-3.1 -2.707,-2.375
  region: -2.707,3.1 -3.008,3.1 -3.008,2.375 -2.707,2.375
  rectangle: -2.373,-3.1 -2.072,-2.375
  region: -2.072,3.1 -2.373,3.1 -2.373,2.375 -2.072,2.375
  rectangle: -1.738,-3.1 -1.437,-2.375
  region: -1.437,3.1 -1.738,3.1 -1.738,2.375 -1.437,2.375
  rectangle: -1.103,-3.1 -0.802,-2.375
  region: -0.802,3.1 -1.103,3.1 -1.103,2.375 -0.802,2.375
  rectangle: -0.468,-3.1 -0.167,-2.375
  region: -0.167,3.1 -0.468,3.1 -0.468,2.375 -0.167,2.375
  rectangle: 0.167,-3.1 0.468,-2.375
  region: 0.468,3.1 0.167,3.1 0.167,2.375 0.468,2.375
  rectangle: 0.802,-3.1 1.103,-2.375
  region: 1.103,3.1 0.802,3.1 0.802,2.375 1.103,2.375
  rectangle: 1.437,-3.1 1.738,-2.375
  region: 1.738,3.1 1.437,3.1 1.437,2.375 1.738,2.375
  rectangle: 2.072,-3.1 2.373,-2.375
  region: 2.373,3.1 2.072,3.1 2.072,2.375 2.373,2.375
  rectangle: 2.707,-3.1 3.008,-2.375
  region: 3.008,3.1 2.707,3.1 2.707,2.375 3.008,2.375
  rectangle: 3.342,-3.1 3.643,-2.375
  region: 3.643,3.1 3.342,3.1 3.342,2.375 3.643,2.375
  rectangle: 3.977,-3.1 4.278,-2.375
  region: 4.278,3.1 3.977,3.1 3.977,2.375 4.278,2.375
  rectangle: 4.612,-3.1 4.913,-2.375
  region: 4.913,3.1 4.612,3.1 4.612,2.375 4.913,2.375
  rectangle: 5.247,-3.1 5.548,-2.375
  region: 5.548,3.1 5.247,3.1 5.247,2.375 5.548,2.375
  rectangle: 5.882,-3.1 6.183,-2.375
  region: 6.183,3.1 5.882,3.1 5.882,2.375 6.183,2.375
  rectangle: 6.517,-3.1 6.818,-2.375
  region: 6.818,3.1 6.517,3.1 6.517,2.375 6.818,2.375
  rectangle: 7.152,-3.1 7.453,-2.375
  region: 7.453,3.1 7.152,3.1 7.152,2.375 7.453,2.375
  rectangle: 7.787,-3.1 8.088,-2.375
  region: 8.088,3.1 7.787,3.1 7.787,2.375 8.088,2.375
  rectangle: 8.422,-3.1 8.723,-2.375
  region: 8.723,3.1 8.422,3.1 8.422,2.375 8.723,2.375
  rectangle: 9.057,-3.1 9.358,-2.375
  region: 9.358,3.1 9.057,3.1 9.057,2.375 9.358,2.375
  rectangle: 9.692,-3.1 9.993,-2.375
  region: 9.993,3.1 9.692,3.1 9.692,2.375 9.993,2.375
  rectangle: 10.327,-3.1 10.628,-2.375
  region: 10.628,3.1 10.327,3.1 10.327,2.375 10.628,2.375
  rectangle: 10.962,-3.1 11.263,-2.375
  region: 11.263,3.1 10.962,3.1 10.962,2.375 11.263,2.375
  rectangle: 11.597,-3.1 11.898,-2.375
  region: 11.898,3.1 11.597,3.1 11.597,2.375 11.898,2.375
  rectangle: 12.232,-3.1 12.533,-2.375
  region: 12.533,3.1 12.232,3.1 12.232,2.375 12.533,2.375
  rectangle: 12.867,-3.1 13.168,-2.375
  region: 13.168,3.1 12.867,3.1 12.867,2.375 13.168,2.375
  rectangle: 13.502,-3.1 13.803,-2.375
  region: 13.803,3.1 13.502,3.1 13.502,2.375 13.803,2.375
  rectangle: 14.137,-3.1 14.438,-2.375
  region: 14.438,3.1 14.137,3.1 14.137,2.375 14.438,2.375
  rectangle: 14.772,-3.1 15.073,-2.375
  region: 15.073,3.1 14.772,3.1 14.772,2.375 15.073,2.375
  rectangle: 15.407,-3.1 15.708,-2.375
  region: 15.708,3.1 15.407,3.1 15.407,2.375 15.708,2.375
  lines w0.203: -19.125,-1.5 -19.125,1.5 ; -17.725,-2.4 17.725,-2.4 ; -17.725,2.4 17.725,2.4 ; -16.125,-2 16.125,-2 ; -16.125,-1 16.125,-1 ; -16.125,1 16.125,1 ; -16.125,2 16.125,2 ; 19.125,-1.5 19.125,1.5

## 52760-1279 [mm]
pads (124):
  round 0.9 hole 0.9: 1(-20.385,0)
  rect 0.35x2.5 smd: 1(-18.732,-2.35) 2(-18.732,2.35) 3(-18.098,-2.35) 4(-18.098,2.35) 5(-17.462,-2.35) 6(-17.462,2.35) 7(-16.828,-2.35) 8(-16.828,2.35) 9(-16.192,-2.35) 10(-16.192,2.35) 11(-15.557,-2.35) 12(-15.557,2.35) 13(-14.922,-2.35) 14(-14.922,2.35) 15(-14.287,-2.35) 16(-14.287,2.35) 17(-13.652,-2.35) 18(-13.652,2.35) 19(-13.018,-2.35) 20(-13.018,2.35) 21(-12.383,-2.35) 22(-12.383,2.35) 23(-11.747,-2.35) 24(-11.747,2.35) 25(-11.112,-2.35) 26(-11.112,2.35) 27(-10.477,-2.35) 28(-10.477,2.35) 29(-9.842,-2.35) 30(-9.842,2.35) 31(-9.207,-2.35) 32(-9.207,2.35) 33(-8.572,-2.35) 34(-8.572,2.35) 35(-7.938,-2.35) 36(-7.938,2.35) 37(-7.302,-2.35) 38(-7.302,2.35) 39(-6.667,-2.35) 40(-6.667,2.35) 41(-6.032,-2.35) 42(-6.032,2.35) 43(-5.397,-2.35) 44(-5.397,2.35) 45(-4.763,-2.35) 46(-4.763,2.35) 47(-4.127,-2.35) 48(-4.127,2.35) 49(-3.492,-2.35) 50(-3.492,2.35) 51(-2.857,-2.35) 52(-2.857,2.35) 53(-2.222,-2.35) 54(-2.222,2.35) 55(-1.587,-2.35) 56(-1.587,2.35) 57(-0.953,-2.35) 58(-0.953,2.35) 59(-0.318,-2.35) 60(-0.318,2.35) 61(0.318,-2.35) 62(0.318,2.35) 63(0.953,-2.35) 64(0.953,2.35) 65(1.587,-2.35) 66(1.587,2.35) 67(2.222,-2.35) 68(2.222,2.35) 69(2.857,-2.35) 70(2.857,2.35) 71(3.492,-2.35) 72(3.492,2.35) 73(4.127,-2.35) 74(4.127,2.35) 75(4.763,-2.35) 76(4.763,2.35) 77(5.397,-2.35) 78(5.397,2.35) 79(6.032,-2.35) 80(6.032,2.35) 81(6.667,-2.35) 82(6.667,2.35) 83(7.302,-2.35) 84(7.302,2.35) 85(7.938,-2.35) 86(7.938,2.35) 87(8.572,-2.35) 88(8.572,2.35) 89(9.207,-2.35) 90(9.207,2.35) 91(9.842,-2.35) 92(9.842,2.35) 93(10.477,-2.35) 94(10.477,2.35) 95(11.112,-2.35) 96(11.112,2.35) 97(11.747,-2.35) 98(11.747,2.35) 99(12.383,-2.35) 100(12.383,2.35) 101(13.018,-2.35) 102(13.018,2.35) 103(13.652,-2.35) 104(13.652,2.35) 105(14.287,-2.35) 106(14.287,2.35) 107(14.922,-2.35) 108(14.922,2.35) 109(15.557,-2.35) 110(15.557,2.35) 111(16.192,-2.35) 112(16.192,2.35) 113(16.828,-2.35) 114(16.828,2.35) 115(17.462,-2.35) 116(17.462,2.35) 117(18.098,-2.35) 118(18.098,2.35) 119(18.732,-2.35) 120(18.732,2.35)
  round 0.7 hole 0.7: 1(20.385,0)
  rect 2.5x2 smd: M1(-22.425,0) M2(22.425,0)
Top Overlay:
  lines w0.203: -22.3,-1.5 -22.9,-1.5 -22.9,-1.9 -21.7,-3.1 -20.9,-3.1 -20.9,-2.4 ; -22.3,1.5 -22.9,1.5 -22.9,3.1 -20.9,3.1 -20.9,2.4 ; -19.3,-2 -21.05,-2 -21.05,0 -20.3,0 -20.3,2 -19.3,2 ; -19.3,-1 cw(c-19.3,-0.75) -19.55,-0.75 -19.55,0.75 cw(c-19.3,0.75) -19.3,1 ; 19.3,-2 21.05,-2 21.05,0 20.3,0 20.3,2 19.3,2 ; 19.3,-1 ccw(c19.3,-0.75) 19.55,-0.75 19.55,0.75 ccw(c19.3,0.75) 19.3,1 ; 20.9,-2.4 20.9,-3.1 22.9,-3.1 22.9,-1.5 22.3,-1.5 ; 20.9,2.4 20.9,3.1 22.9,3.1 22.9,1.5 22.3,1.5
Top Solder:
  rectangle: -18.932,-3.625 -18.533,-1.075
  region: -18.533,3.625 -18.932,3.625 -18.932,1.075 -18.533,1.075
  rectangle: -18.297,-3.625 -17.898,-1.075
  region: -17.898,3.625 -18.297,3.625 -18.297,1.075 -17.898,1.075
  rectangle: -17.662,-3.625 -17.263,-1.075
  region: -17.263,3.625 -17.662,3.625 -17.662,1.075 -17.263,1.075
  rectangle: -17.027,-3.625 -16.628,-1.075
  region: -16.628,3.625 -17.027,3.625 -17.027,1.075 -16.628,1.075
  rectangle: -16.392,-3.625 -15.993,-1.075
  region: -15.993,3.625 -16.392,3.625 -16.392,1.075 -15.993,1.075
  rectangle: -15.757,-3.625 -15.358,-1.075
  region: -15.358,3.625 -15.757,3.625 -15.757,1.075 -15.358,1.075
  rectangle: -15.122,-3.625 -14.723,-1.075
  region: -14.723,3.625 -15.122,3.625 -15.122,1.075 -14.723,1.075
  rectangle: -14.487,-3.625 -14.088,-1.075
  region: -14.088,3.625 -14.487,3.625 -14.487,1.075 -14.088,1.075
  rectangle: -13.852,-3.625 -13.453,-1.075
  region: -13.453,3.625 -13.852,3.625 -13.852,1.075 -13.453,1.075
  rectangle: -13.217,-3.625 -12.818,-1.075
  region: -12.818,3.625 -13.217,3.625 -13.217,1.075 -12.818,1.075
  rectangle: -12.582,-3.625 -12.183,-1.075
  region: -12.183,3.625 -12.582,3.625 -12.582,1.075 -12.183,1.075
  rectangle: -11.947,-3.625 -11.548,-1.075
  region: -11.548,3.625 -11.947,3.625 -11.947,1.075 -11.548,1.075
  rectangle: -11.312,-3.625 -10.913,-1.075
  region: -10.913,3.625 -11.312,3.625 -11.312,1.075 -10.913,1.075
  rectangle: -10.677,-3.625 -10.278,-1.075
  region: -10.278,3.625 -10.677,3.625 -10.677,1.075 -10.278,1.075
  rectangle: -10.042,-3.625 -9.643,-1.075
  region: -9.643,3.625 -10.042,3.625 -10.042,1.075 -9.643,1.075
  rectangle: -9.407,-3.625 -9.008,-1.075
  region: -9.008,3.625 -9.407,3.625 -9.407,1.075 -9.008,1.075
  rectangle: -8.772,-3.625 -8.373,-1.075
  region: -8.373,3.625 -8.772,3.625 -8.772,1.075 -8.373,1.075
  rectangle: -8.137,-3.625 -7.738,-1.075
  region: -7.738,3.625 -8.137,3.625 -8.137,1.075 -7.738,1.075
  rectangle: -7.502,-3.625 -7.103,-1.075
  region: -7.103,3.625 -7.502,3.625 -7.502,1.075 -7.103,1.075
  rectangle: -6.867,-3.625 -6.468,-1.075
  region: -6.468,3.625 -6.867,3.625 -6.867,1.075 -6.468,1.075
  rectangle: -6.232,-3.625 -5.833,-1.075
  region: -5.833,3.625 -6.232,3.625 -6.232,1.075 -5.833,1.075
  rectangle: -5.597,-3.625 -5.198,-1.075
  region: -5.198,3.625 -5.597,3.625 -5.597,1.075 -5.198,1.075
  rectangle: -4.962,-3.625 -4.563,-1.075
  region: -4.563,3.625 -4.962,3.625 -4.962,1.075 -4.563,1.075
  rectangle: -4.327,-3.625 -3.928,-1.075
  region: -3.928,3.625 -4.327,3.625 -4.327,1.075 -3.928,1.075
  rectangle: -3.692,-3.625 -3.293,-1.075
  region: -3.293,3.625 -3.692,3.625 -3.692,1.075 -3.293,1.075
  rectangle: -3.057,-3.625 -2.658,-1.075
  region: -2.658,3.625 -3.057,3.625 -3.057,1.075 -2.658,1.075
  rectangle: -2.422,-3.625 -2.023,-1.075
  region: -2.023,3.625 -2.422,3.625 -2.422,1.075 -2.023,1.075
  rectangle: -1.787,-3.625 -1.388,-1.075
  region: -1.388,3.625 -1.787,3.625 -1.787,1.075 -1.388,1.075
  rectangle: -1.152,-3.625 -0.753,-1.075
  region: -0.753,3.625 -1.152,3.625 -1.152,1.075 -0.753,1.075
  rectangle: -0.517,-3.625 -0.118,-1.075
  region: -0.118,3.625 -0.517,3.625 -0.517,1.075 -0.118,1.075
  rectangle: 0.118,-3.625 0.517,-1.075
  region: 0.517,3.625 0.118,3.625 0.118,1.075 0.517,1.075
  rectangle: 0.753,-3.625 1.152,-1.075
  region: 1.152,3.625 0.753,3.625 0.753,1.075 1.152,1.075
  rectangle: 1.388,-3.625 1.787,-1.075
  region: 1.787,3.625 1.388,3.625 1.388,1.075 1.787,1.075
  rectangle: 2.023,-3.625 2.422,-1.075
  region: 2.422,3.625 2.023,3.625 2.023,1.075 2.422,1.075
  rectangle: 2.658,-3.625 3.057,-1.075
  region: 3.057,3.625 2.658,3.625 2.658,1.075 3.057,1.075
  rectangle: 3.293,-3.625 3.692,-1.075
  region: 3.692,3.625 3.293,3.625 3.293,1.075 3.692,1.075
  rectangle: 3.928,-3.625 4.327,-1.075
  region: 4.327,3.625 3.928,3.625 3.928,1.075 4.327,1.075
  rectangle: 4.563,-3.625 4.962,-1.075
  region: 4.962,3.625 4.563,3.625 4.563,1.075 4.962,1.075
  rectangle: 5.198,-3.625 5.597,-1.075
  region: 5.597,3.625 5.198,3.625 5.198,1.075 5.597,1.075
  rectangle: 5.833,-3.625 6.232,-1.075
  region: 6.232,3.625 5.833,3.625 5.833,1.075 6.232,1.075
  rectangle: 6.468,-3.625 6.867,-1.075
  region: 6.867,3.625 6.468,3.625 6.468,1.075 6.867,1.075
  rectangle: 7.103,-3.625 7.502,-1.075
  region: 7.502,3.625 7.103,3.625 7.103,1.075 7.502,1.075
  rectangle: 7.738,-3.625 8.137,-1.075
  region: 8.137,3.625 7.738,3.625 7.738,1.075 8.137,1.075
  rectangle: 8.373,-3.625 8.772,-1.075
  region: 8.772,3.625 8.373,3.625 8.373,1.075 8.772,1.075
  rectangle: 9.008,-3.625 9.407,-1.075
  region: 9.407,3.625 9.008,3.625 9.008,1.075 9.407,1.075
  rectangle: 9.643,-3.625 10.042,-1.075
  region: 10.042,3.625 9.643,3.625 9.643,1.075 10.042,1.075
  rectangle: 10.278,-3.625 10.677,-1.075
  region: 10.677,3.625 10.278,3.625 10.278,1.075 10.677,1.075
  rectangle: 10.913,-3.625 11.312,-1.075
  region: 11.312,3.625 10.913,3.625 10.913,1.075 11.312,1.075
  rectangle: 11.548,-3.625 11.947,-1.075
  region: 11.947,3.625 11.548,3.625 11.548,1.075 11.947,1.075
  rectangle: 12.183,-3.625 12.582,-1.075
  region: 12.582,3.625 12.183,3.625 12.183,1.075 12.582,1.075
  rectangle: 12.818,-3.625 13.217,-1.075
  region: 13.217,3.625 12.818,3.625 12.818,1.075 13.217,1.075
  rectangle: 13.453,-3.625 13.852,-1.075
  region: 13.852,3.625 13.453,3.625 13.453,1.075 13.852,1.075
  rectangle: 14.088,-3.625 14.487,-1.075
  region: 14.487,3.625 14.088,3.625 14.088,1.075 14.487,1.075
  rectangle: 14.723,-3.625 15.122,-1.075
  region: 15.122,3.625 14.723,3.625 14.723,1.075 15.122,1.075
  rectangle: 15.358,-3.625 15.757,-1.075
  region: 15.757,3.625 15.358,3.625 15.358,1.075 15.757,1.075
  rectangle: 15.993,-3.625 16.392,-1.075
  region: 16.392,3.625 15.993,3.625 15.993,1.075 16.392,1.075
  rectangle: 16.628,-3.625 17.027,-1.075
  region: 17.027,3.625 16.628,3.625 16.628,1.075 17.027,1.075
  rectangle: 17.263,-3.625 17.662,-1.075
  region: 17.662,3.625 17.263,3.625 17.263,1.075 17.662,1.075
  rectangle: 17.898,-3.625 18.297,-1.075
  region: 18.297,3.625 17.898,3.625 17.898,1.075 18.297,1.075
  rectangle: 18.533,-3.625 18.932,-1.075
  region: 18.932,3.625 18.533,3.625 18.533,1.075 18.932,1.075
Mechanical 16:
  rectangle: -18.883,-3.1 -18.582,-2.375
  region: -18.582,3.1 -18.883,3.1 -18.883,2.375 -18.582,2.375
  rectangle: -18.248,-3.1 -17.947,-2.375
  region: -17.947,3.1 -18.248,3.1 -18.248,2.375 -17.947,2.375
  rectangle: -17.613,-3.1 -17.312,-2.375
  region: -17.312,3.1 -17.613,3.1 -17.613,2.375 -17.312,2.375
  rectangle: -16.978,-3.1 -16.677,-2.375
  region: -16.677,3.1 -16.978,3.1 -16.978,2.375 -16.677,2.375
  rectangle: -16.343,-3.1 -16.042,-2.375
  region: -16.042,3.1 -16.343,3.1 -16.343,2.375 -16.042,2.375
  rectangle: -15.708,-3.1 -15.407,-2.375
  region: -15.407,3.1 -15.708,3.1 -15.708,2.375 -15.407,2.375
  rectangle: -15.073,-3.1 -14.772,-2.375
  region: -14.772,3.1 -15.073,3.1 -15.073,2.375 -14.772,2.375
  rectangle: -14.438,-3.1 -14.137,-2.375
  region: -14.137,3.1 -14.438,3.1 -14.438,2.375 -14.137,2.375
  rectangle: -13.803,-3.1 -13.502,-2.375
  region: -13.502,3.1 -13.803,3.1 -13.803,2.375 -13.502,2.375
  rectangle: -13.168,-3.1 -12.867,-2.375
  region: -12.867,3.1 -13.168,3.1 -13.168,2.375 -12.867,2.375
  rectangle: -12.533,-3.1 -12.232,-2.375
  region: -12.232,3.1 -12.533,3.1 -12.533,2.375 -12.232,2.375
  rectangle: -11.898,-3.1 -11.597,-2.375
  region: -11.597,3.1 -11.898,3.1 -11.898,2.375 -11.597,2.375
  rectangle: -11.263,-3.1 -10.962,-2.375
  region: -10.962,3.1 -11.263,3.1 -11.263,2.375 -10.962,2.375
  rectangle: -10.628,-3.1 -10.327,-2.375
  region: -10.327,3.1 -10.628,3.1 -10.628,2.375 -10.327,2.375
  rectangle: -9.993,-3.1 -9.692,-2.375
  region: -9.692,3.1 -9.993,3.1 -9.993,2.375 -9.692,2.375
  rectangle: -9.358,-3.1 -9.057,-2.375
  region: -9.057,3.1 -9.358,3.1 -9.358,2.375 -9.057,2.375
  rectangle: -8.723,-3.1 -8.422,-2.375
  region: -8.422,3.1 -8.723,3.1 -8.723,2.375 -8.422,2.375
  rectangle: -8.088,-3.1 -7.787,-2.375
  region: -7.787,3.1 -8.088,3.1 -8.088,2.375 -7.787,2.375
  rectangle: -7.453,-3.1 -7.152,-2.375
  region: -7.152,3.1 -7.453,3.1 -7.453,2.375 -7.152,2.375
  rectangle: -6.818,-3.1 -6.517,-2.375
  region: -6.517,3.1 -6.818,3.1 -6.818,2.375 -6.517,2.375
  rectangle: -6.183,-3.1 -5.882,-2.375
  region: -5.882,3.1 -6.183,3.1 -6.183,2.375 -5.882,2.375
  rectangle: -5.548,-3.1 -5.247,-2.375
  region: -5.247,3.1 -5.548,3.1 -5.548,2.375 -5.247,2.375
  rectangle: -4.913,-3.1 -4.612,-2.375
  region: -4.612,3.1 -4.913,3.1 -4.913,2.375 -4.612,2.375
  rectangle: -4.278,-3.1 -3.977,-2.375
  region: -3.977,3.1 -4.278,3.1 -4.278,2.375 -3.977,2.375
  rectangle: -3.643,-3.1 -3.342,-2.375
  region: -3.342,3.1 -3.643,3.1 -3.643,2.375 -3.342,2.375
  rectangle: -3.008,-3.1 -2.707,-2.375
  region: -2.707,3.1 -3.008,3.1 -3.008,2.375 -2.707,2.375
  rectangle: -2.373,-3.1 -2.072,-2.375
  region: -2.072,3.1 -2.373,3.1 -2.373,2.375 -2.072,2.375
  rectangle: -1.738,-3.1 -1.437,-2.375
  region: -1.437,3.1 -1.738,3.1 -1.738,2.375 -1.437,2.375
  rectangle: -1.103,-3.1 -0.802,-2.375
  region: -0.802,3.1 -1.103,3.1 -1.103,2.375 -0.802,2.375
  rectangle: -0.468,-3.1 -0.167,-2.375
  region: -0.167,3.1 -0.468,3.1 -0.468,2.375 -0.167,2.375
  rectangle: 0.167,-3.1 0.468,-2.375
  region: 0.468,3.1 0.167,3.1 0.167,2.375 0.468,2.375
  rectangle: 0.802,-3.1 1.103,-2.375
  region: 1.103,3.1 0.802,3.1 0.802,2.375 1.103,2.375
  rectangle: 1.437,-3.1 1.738,-2.375
  region: 1.738,3.1 1.437,3.1 1.437,2.375 1.738,2.375
  rectangle: 2.072,-3.1 2.373,-2.375
  region: 2.373,3.1 2.072,3.1 2.072,2.375 2.373,2.375
  rectangle: 2.707,-3.1 3.008,-2.375
  region: 3.008,3.1 2.707,3.1 2.707,2.375 3.008,2.375
  rectangle: 3.342,-3.1 3.643,-2.375
  region: 3.643,3.1 3.342,3.1 3.342,2.375 3.643,2.375
  rectangle: 3.977,-3.1 4.278,-2.375
  region: 4.278,3.1 3.977,3.1 3.977,2.375 4.278,2.375
  rectangle: 4.612,-3.1 4.913,-2.375
  region: 4.913,3.1 4.612,3.1 4.612,2.375 4.913,2.375
  rectangle: 5.247,-3.1 5.548,-2.375
  region: 5.548,3.1 5.247,3.1 5.247,2.375 5.548,2.375
  rectangle: 5.882,-3.1 6.183,-2.375
  region: 6.183,3.1 5.882,3.1 5.882,2.375 6.183,2.375
  rectangle: 6.517,-3.1 6.818,-2.375
  region: 6.818,3.1 6.517,3.1 6.517,2.375 6.818,2.375
  rectangle: 7.152,-3.1 7.453,-2.375
  region: 7.453,3.1 7.152,3.1 7.152,2.375 7.453,2.375
  rectangle: 7.787,-3.1 8.088,-2.375
  region: 8.088,3.1 7.787,3.1 7.787,2.375 8.088,2.375
  rectangle: 8.422,-3.1 8.723,-2.375
  region: 8.723,3.1 8.422,3.1 8.422,2.375 8.723,2.375
  rectangle: 9.057,-3.1 9.358,-2.375
  region: 9.358,3.1 9.057,3.1 9.057,2.375 9.358,2.375
  rectangle: 9.692,-3.1 9.993,-2.375
  region: 9.993,3.1 9.692,3.1 9.692,2.375 9.993,2.375
  rectangle: 10.327,-3.1 10.628,-2.375
  region: 10.628,3.1 10.327,3.1 10.327,2.375 10.628,2.375
  rectangle: 10.962,-3.1 11.263,-2.375
  region: 11.263,3.1 10.962,3.1 10.962,2.375 11.263,2.375
  rectangle: 11.597,-3.1 11.898,-2.375
  region: 11.898,3.1 11.597,3.1 11.597,2.375 11.898,2.375
  rectangle: 12.232,-3.1 12.533,-2.375
  region: 12.533,3.1 12.232,3.1 12.232,2.375 12.533,2.375
  rectangle: 12.867,-3.1 13.168,-2.375
  region: 13.168,3.1 12.867,3.1 12.867,2.375 13.168,2.375
  rectangle: 13.502,-3.1 13.803,-2.375
  region: 13.803,3.1 13.502,3.1 13.502,2.375 13.803,2.375
  rectangle: 14.137,-3.1 14.438,-2.375
  region: 14.438,3.1 14.137,3.1 14.137,2.375 14.438,2.375
  rectangle: 14.772,-3.1 15.073,-2.375
  region: 15.073,3.1 14.772,3.1 14.772,2.375 15.073,2.375
  rectangle: 15.407,-3.1 15.708,-2.375
  region: 15.708,3.1 15.407,3.1 15.407,2.375 15.708,2.375
  rectangle: 16.042,-3.1 16.343,-2.375
  region: 16.343,3.1 16.042,3.1 16.042,2.375 16.343,2.375
  rectangle: 16.677,-3.1 16.978,-2.375
  region: 16.978,3.1 16.677,3.1 16.677,2.375 16.978,2.375
  rectangle: 17.312,-3.1 17.613,-2.375
  region: 17.613,3.1 17.312,3.1 17.312,2.375 17.613,2.375
  rectangle: 17.947,-3.1 18.248,-2.375
  region: 18.248,3.1 17.947,3.1 17.947,2.375 18.248,2.375
  rectangle: 18.582,-3.1 18.883,-2.375
  region: 18.883,3.1 18.582,3.1 18.582,2.375 18.883,2.375
  lines w0.203: -22.3,-1.5 -22.3,1.5 ; -20.9,-2.4 20.9,-2.4 ; -20.9,2.4 20.9,2.4 ; -19.3,-2 19.3,-2 ; -19.3,-1 19.3,-1 ; -19.3,1 19.3,1 ; -19.3,2 19.3,2 ; 22.3,-1.5 22.3,1.5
